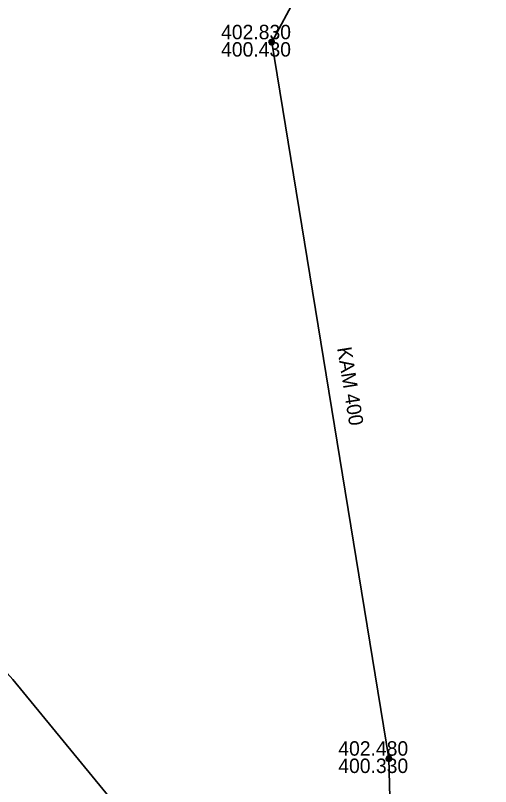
# Model space of a CAD drawing. Extents: x -873619 to -867639, y -1015082 to -1012326.
# Drawn here: x -867896.5 to -867860.4, y -1012817 to -1012758.3 of the extents above; entities that cross this region are included whole.
import ezdxf

# ---------------------------------------------------------------- set-up
doc = ezdxf.new("R2010")
doc.units = 0
doc.header["$LTSCALE"] = 0.44
for name, color, linetype, lineweight in [('1', 7, 'Continuous', 13), ('21', 7, 'Continuous', 35), ('32', 7, 'Continuous', 13)]:
    doc.layers.add(name, color=color, linetype=linetype, lineweight=lineweight)

msp = doc.modelspace()

# ---------------------------------------------------------------- linework, layer by layer
at = {"layer": '21'}
for p, q in [((-867860.38, -1012729.43), (-867877.04, -1012760.3)), ((-867877.04, -1012760.3), (-867868.119, -1012814.87))]:
    msp.add_line(p, q, dxfattribs=at)
for points in [[(-867931.383, -1012770.263), (-867896.732, -1012808.835), (-867867.37, -1012844.68)], [(-867868.119, -1012814.87), (-867867.37, -1012844.68), (-867869.709, -1012883.46), (-867874.376, -1012932.352)]]:
    msp.add_lwpolyline(points, dxfattribs=at)
at = {"layer": '32'}
for points in [[(-867876.809, -1012760.3), (-867876.815, -1012760.248), (-867876.832, -1012760.198), (-867876.861, -1012760.154), (-867876.898, -1012760.117), (-867876.943, -1012760.09), (-867876.993, -1012760.073), (-867877.046, -1012760.069), (-867877.098, -1012760.076), (-867877.147, -1012760.095), (-867877.19, -1012760.124), (-867877.226, -1012760.163), (-867877.252, -1012760.208), (-867877.268, -1012760.259), (-867877.271, -1012760.311), (-867877.263, -1012760.363), (-867877.243, -1012760.412), (-867877.212, -1012760.455), (-867877.173, -1012760.489), (-867877.127, -1012760.515), (-867877.076, -1012760.529), (-867877.023, -1012760.531), (-867876.972, -1012760.521), (-867876.924, -1012760.5), (-867876.881, -1012760.469), (-867876.847, -1012760.428), (-867876.823, -1012760.382), (-867876.811, -1012760.331)], [(-867876.839, -1012760.3), (-867876.845, -1012760.251), (-867876.862, -1012760.205), (-867876.89, -1012760.165), (-867876.927, -1012760.133), (-867876.971, -1012760.111), (-867877.019, -1012760.1), (-867877.068, -1012760.1), (-867877.115, -1012760.113), (-867877.158, -1012760.137), (-867877.194, -1012760.17), (-867877.221, -1012760.211), (-867877.237, -1012760.258), (-867877.241, -1012760.307), (-867877.234, -1012760.355), (-867877.215, -1012760.4), (-867877.185, -1012760.44), (-867877.147, -1012760.471), (-867877.103, -1012760.491), (-867877.055, -1012760.501), (-867877.006, -1012760.499), (-867876.959, -1012760.484), (-867876.916, -1012760.459), (-867876.882, -1012760.425), (-867876.856, -1012760.383), (-867876.842, -1012760.336)], [(-867876.869, -1012760.3), (-867876.875, -1012760.255), (-867876.892, -1012760.213), (-867876.92, -1012760.178), (-867876.956, -1012760.151), (-867876.998, -1012760.134), (-867877.043, -1012760.129), (-867877.088, -1012760.135), (-867877.129, -1012760.154), (-867877.164, -1012760.182), (-867877.191, -1012760.219), (-867877.207, -1012760.261), (-867877.211, -1012760.306), (-867877.204, -1012760.351), (-867877.185, -1012760.392), (-867877.156, -1012760.426), (-867877.119, -1012760.452), (-867877.076, -1012760.468), (-867877.031, -1012760.471), (-867876.986, -1012760.463), (-867876.946, -1012760.443), (-867876.912, -1012760.414), (-867876.886, -1012760.376), (-867876.872, -1012760.333)], [(-867876.899, -1012760.3), (-867876.904, -1012760.259), (-867876.922, -1012760.222), (-867876.949, -1012760.191), (-867876.984, -1012760.17), (-867877.024, -1012760.159), (-867877.065, -1012760.161), (-867877.104, -1012760.174), (-867877.138, -1012760.198), (-867877.163, -1012760.23), (-867877.178, -1012760.268), (-867877.181, -1012760.309), (-867877.173, -1012760.349), (-867877.153, -1012760.385), (-867877.124, -1012760.414), (-867877.087, -1012760.433), (-867877.047, -1012760.441), (-867877.006, -1012760.437), (-867876.968, -1012760.422), (-867876.936, -1012760.396), (-867876.913, -1012760.362), (-867876.9, -1012760.323)], [(-867876.929, -1012760.3), (-867876.934, -1012760.264), (-867876.952, -1012760.232), (-867876.978, -1012760.207), (-867877.012, -1012760.192), (-867877.048, -1012760.189), (-867877.083, -1012760.197), (-867877.114, -1012760.217), (-867877.137, -1012760.245), (-867877.15, -1012760.279), (-867877.15, -1012760.316), (-867877.139, -1012760.351), (-867877.118, -1012760.38), (-867877.088, -1012760.401), (-867877.053, -1012760.411), (-867877.016, -1012760.409), (-867876.982, -1012760.395), (-867876.955, -1012760.372), (-867876.936, -1012760.34), (-867876.929, -1012760.305)], [(-867876.959, -1012760.3), (-867876.964, -1012760.269), (-867876.981, -1012760.243), (-867877.007, -1012760.226), (-867877.037, -1012760.219), (-867877.068, -1012760.223), (-867877.095, -1012760.24), (-867877.113, -1012760.264), (-867877.121, -1012760.295), (-867877.117, -1012760.325), (-867877.102, -1012760.353), (-867877.078, -1012760.372), (-867877.048, -1012760.381), (-867877.017, -1012760.378), (-867876.989, -1012760.364), (-867876.969, -1012760.34), (-867876.959, -1012760.311)], [(-867876.989, -1012760.3), (-867876.994, -1012760.276), (-867877.011, -1012760.258), (-867877.034, -1012760.249), (-867877.058, -1012760.252), (-867877.079, -1012760.266), (-867877.09, -1012760.288), (-867877.09, -1012760.313), (-867877.078, -1012760.334), (-867877.058, -1012760.348), (-867877.033, -1012760.351), (-867877.01, -1012760.342), (-867876.994, -1012760.324)], [(-867877.019, -1012760.3), (-867877.024, -1012760.285), (-867877.039, -1012760.279), (-867877.054, -1012760.283), (-867877.061, -1012760.297), (-867877.057, -1012760.312), (-867877.044, -1012760.321), (-867877.029, -1012760.318), (-867877.019, -1012760.306)], [(-867867.887, -1012814.87), (-867867.894, -1012814.818), (-867867.911, -1012814.768), (-867867.94, -1012814.724), (-867867.977, -1012814.687), (-867868.022, -1012814.66), (-867868.071, -1012814.643), (-867868.125, -1012814.639), (-867868.176, -1012814.646), (-867868.225, -1012814.665), (-867868.269, -1012814.694), (-867868.304, -1012814.733), (-867868.331, -1012814.778), (-867868.347, -1012814.829), (-867868.35, -1012814.881), (-867868.342, -1012814.933), (-867868.321, -1012814.982), (-867868.291, -1012815.025), (-867868.252, -1012815.059), (-867868.206, -1012815.085), (-867868.154, -1012815.099), (-867868.102, -1012815.101), (-867868.051, -1012815.091), (-867868.002, -1012815.07), (-867867.96, -1012815.039), (-867867.926, -1012814.998), (-867867.902, -1012814.952), (-867867.889, -1012814.901)], [(-867867.918, -1012814.87), (-867867.924, -1012814.821), (-867867.941, -1012814.775), (-867867.968, -1012814.735), (-867868.005, -1012814.703), (-867868.049, -1012814.681), (-867868.098, -1012814.67), (-867868.147, -1012814.67), (-867868.193, -1012814.683), (-867868.237, -1012814.707), (-867868.272, -1012814.74), (-867868.299, -1012814.781), (-867868.316, -1012814.828), (-867868.32, -1012814.877), (-867868.313, -1012814.925), (-867868.294, -1012814.97), (-867868.264, -1012815.01), (-867868.225, -1012815.041), (-867868.181, -1012815.061), (-867868.134, -1012815.071), (-867868.085, -1012815.069), (-867868.038, -1012815.054), (-867867.995, -1012815.029), (-867867.96, -1012814.995), (-867867.934, -1012814.953), (-867867.921, -1012814.906)], [(-867867.948, -1012814.87), (-867867.953, -1012814.825), (-867867.97, -1012814.783), (-867867.999, -1012814.748), (-867868.034, -1012814.721), (-867868.076, -1012814.704), (-867868.122, -1012814.699), (-867868.166, -1012814.705), (-867868.208, -1012814.724), (-867868.242, -1012814.752), (-867868.269, -1012814.789), (-867868.286, -1012814.831), (-867868.289, -1012814.876), (-867868.282, -1012814.921), (-867868.264, -1012814.962), (-867868.235, -1012814.996), (-867868.198, -1012815.022), (-867868.154, -1012815.038), (-867868.11, -1012815.041), (-867868.065, -1012815.033), (-867868.024, -1012815.013), (-867867.99, -1012814.984), (-867867.965, -1012814.946), (-867867.951, -1012814.903)], [(-867867.978, -1012814.87), (-867867.982, -1012814.829), (-867868, -1012814.792), (-867868.027, -1012814.761), (-867868.063, -1012814.74), (-867868.103, -1012814.729), (-867868.144, -1012814.731), (-867868.183, -1012814.744), (-867868.217, -1012814.768), (-867868.242, -1012814.8), (-867868.257, -1012814.838), (-867868.259, -1012814.879), (-867868.252, -1012814.919), (-867868.232, -1012814.955), (-867868.203, -1012814.984), (-867868.166, -1012815.003), (-867868.125, -1012815.011), (-867868.085, -1012815.007), (-867868.046, -1012814.992), (-867868.014, -1012814.966), (-867867.992, -1012814.932), (-867867.978, -1012814.893)], [(-867868.007, -1012814.87), (-867868.012, -1012814.834), (-867868.031, -1012814.802), (-867868.056, -1012814.777), (-867868.09, -1012814.762), (-867868.127, -1012814.759), (-867868.161, -1012814.767), (-867868.193, -1012814.787), (-867868.215, -1012814.815), (-867868.228, -1012814.849), (-867868.228, -1012814.886), (-867868.218, -1012814.921), (-867868.196, -1012814.95), (-867868.166, -1012814.971), (-867868.132, -1012814.981), (-867868.095, -1012814.979), (-867868.061, -1012814.965), (-867868.034, -1012814.942), (-867868.014, -1012814.91), (-867868.007, -1012814.875)], [(-867868.038, -1012814.87), (-867868.043, -1012814.839), (-867868.059, -1012814.813), (-867868.085, -1012814.796), (-867868.115, -1012814.789), (-867868.147, -1012814.793), (-867868.174, -1012814.81), (-867868.191, -1012814.834), (-867868.2, -1012814.865), (-867868.196, -1012814.895), (-867868.181, -1012814.923), (-867868.156, -1012814.942), (-867868.127, -1012814.951), (-867868.095, -1012814.948), (-867868.068, -1012814.934), (-867868.048, -1012814.91), (-867868.038, -1012814.881)], [(-867868.068, -1012814.87), (-867868.073, -1012814.846), (-867868.09, -1012814.828), (-867868.112, -1012814.819), (-867868.137, -1012814.822), (-867868.157, -1012814.836), (-867868.169, -1012814.858), (-867868.169, -1012814.883), (-867868.156, -1012814.904), (-867868.137, -1012814.918), (-867868.112, -1012814.921), (-867868.088, -1012814.912), (-867868.073, -1012814.894)], [(-867868.098, -1012814.87), (-867868.103, -1012814.855), (-867868.117, -1012814.849), (-867868.132, -1012814.853), (-867868.139, -1012814.867), (-867868.136, -1012814.882), (-867868.122, -1012814.891), (-867868.107, -1012814.888), (-867868.098, -1012814.876)]]:
    msp.add_lwpolyline(points, close=True, dxfattribs=at)

# ---------------------------------------------------------------- texts
at = {"layer": '1'}
for s, p in [('402.830 ', (-867880.89, -1012760.08)), ('400.430 ', (-867880.89, -1012761.4)), ('402.480 ', (-867871.969, -1012814.65)), ('400.330 ', (-867871.969, -1012815.97))]:
    msp.add_text(s, height=1.1, dxfattribs=at).set_placement(p)
msp.add_text('KAM 400 ', height=1.1, rotation=279, dxfattribs=at).set_placement((-867872.065, -1012783.599))

doc.saveas('drawing.dxf')
